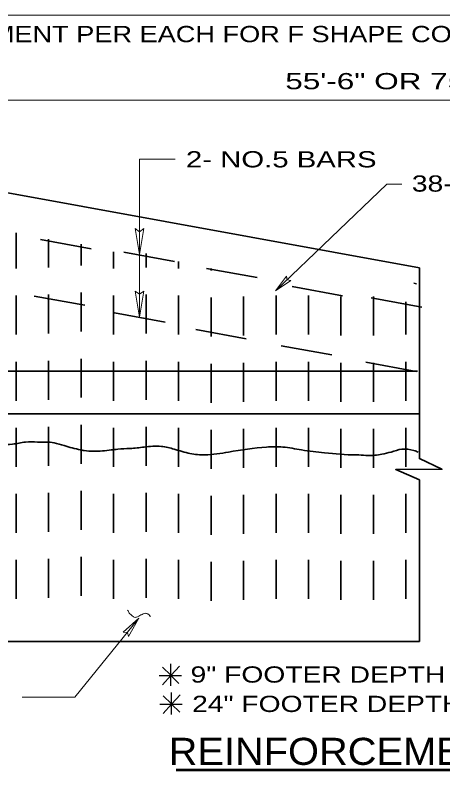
# Model space of a CAD drawing. Extents: x -15.1 to -7.9, y 13.6 to 23.8.
# Drawn here: x -13.275 to -11.694, y 16.811 to 19.599 of the extents above; entities that cross this region are included whole.
import ezdxf
from ezdxf.enums import TextEntityAlignment as Align

# ---------------------------------------------------------------- set-up
doc = ezdxf.new("R2010")
doc.units = 0
doc.header["$LTSCALE"] = 0.024
doc.linetypes.add('LONG_DASHED', pattern=[7.5, 6, -1.5])
for name, color, linetype, lineweight in [('1', 7, 'Continuous', 35), ('10', 7, 'Continuous', 13), ('12', 7, 'Continuous', 53)]:
    doc.layers.add(name, color=color, linetype=linetype, lineweight=lineweight)

msp = doc.modelspace()

# ---------------------------------------------------------------- linework, layer by layer
at = {"layer": '1'}
for p, q in [((-11.781, 18.666), (-13.76133, 19.026)), ((-12.99417, 18.73567), (-13.18083, 18.76967)), ((-12.686, 18.68917), (-12.87283, 18.723)), ((-12.3805, 18.6295), (-12.56717, 18.6635)), ((-11.79167, 18.60683), (-11.8015, 18.60867)), ((-12.0645, 18.56217), (-12.25133, 18.59617)), ((-13.0175, 18.52733), (-13.20417, 18.56133)), ((-11.772, 18.52083), (-11.95883, 18.55467)), ((-12.72083, 18.4655), (-12.90767, 18.4995)), ((-12.4205, 18.40333), (-12.60717, 18.43733)), ((-12.1045, 18.34383), (-12.29133, 18.37783)), ((-11.79233, 18.28283), (-11.97917, 18.31683)), ((-11.78733, 18.28383), (-14.11333, 18.28383)), ((-11.781, 18.12583), (-14.12133, 18.12583)), ((-11.781, 17.88333), (-11.781, 17.88417)), ((-11.781, 17.28567), (-14.12133, 17.28567))]:
    msp.add_line(p, q, dxfattribs=at)
at = {"layer": '1', "linetype": 'LONG_DASHED'}
for p, q in [((-13.27083, 17.44283), (-13.27083, 18.7945)), ((-13.15083, 17.4465), (-13.15083, 18.771)), ((-13.03083, 17.454), (-13.03083, 18.7535)), ((-12.91083, 17.44283), (-12.91083, 18.72417)), ((-12.79083, 17.4465), (-12.79083, 18.71833)), ((-12.67083, 17.44283), (-12.67083, 18.689)), ((-12.55067, 17.4355), (-12.55067, 18.66267)), ((-12.43067, 17.43917), (-12.43067, 18.642)), ((-12.31067, 17.44283), (-12.31067, 18.6215)), ((-12.19067, 17.44283), (-12.19067, 18.58933)), ((-12.07067, 17.43917), (-12.07067, 18.56883)), ((-11.95067, 17.43917), (-11.95067, 18.56)), ((-11.83067, 17.44283), (-11.83067, 18.5395))]:
    msp.add_line(p, q, dxfattribs=at)
at = {"layer": '1'}
msp.add_spline([(-14.12217, 18.03783), (-14.101, 18.03517), (-14.072, 18.03517), (-14.04283, 18.0405), (-14.0165, 18.0405), (-13.99267, 18.0405), (-13.95833, 18.0405), (-13.916, 18.0325), (-13.86833, 18.02733), (-13.8235, 18.02467), (-13.79167, 18.022), (-13.76267, 18.022), (-13.71767, 18.02733), (-13.678, 18.02983), (-13.63583, 18.0325), (-13.58817, 18.0325), (-13.5485, 18.02983), (-13.501, 18.022), (-13.456, 18.01417), (-13.40317, 18.00883), (-13.3635, 18.00883), (-13.329, 18.0115), (-13.28417, 18.01417), (-13.2365, 18.022), (-13.19167, 18.022), (-13.13083, 18.01933), (-13.09383, 18.00883), (-13.033, 17.993), (-13.01983, 17.99033), (-12.9855, 17.98783), (-12.91933, 17.993), (-12.8955, 17.99567), (-12.85067, 17.99833), (-12.79767, 18.0035), (-12.73433, 18.00617), (-12.68667, 17.99567), (-12.6285, 17.97983), (-12.573, 17.97467), (-12.48583, 17.98517), (-12.34567, 18.0035), (-12.28483, 18.0035), (-12.21617, 17.993), (-12.1315, 17.9825), (-12.01517, 17.97467), (-12.01267, 17.97467), (-12.00467, 17.97467), (-11.97033, 17.972), (-11.92, 17.97733), (-11.88567, 17.98517), (-11.846, 17.99567), (-11.801, 17.99033), (-11.78517, 17.98517)], degree=3, dxfattribs=at)
at = {"layer": '10'}
for p, q in [((-13.76867, 19.59917), (-8.606, 19.59917)), ((-10.09083, 19.28517), (-13.63867, 19.28517)), ((-11.90117, 18.97517), (-12.31217, 18.5805)), ((-11.84517, 18.975), (-11.90117, 18.975)), ((-12.83083, 18.8105), (-12.81483, 18.7145)), ((-12.83083, 18.8105), (-12.81483, 18.7985)), ((-12.79883, 18.8105), (-12.81483, 18.7145)), ((-12.79883, 18.8105), (-12.81483, 18.7985)), ((-12.2715, 18.63517), (-12.31217, 18.5805)), ((-12.2715, 18.63517), (-12.26983, 18.62133)), ((-12.256, 18.619), (-12.31217, 18.5805)), ((-12.256, 18.619), (-12.26983, 18.62133)), ((-12.83083, 18.57983), (-12.81483, 18.48383)), ((-12.83083, 18.57983), (-12.81483, 18.56783)), ((-12.79883, 18.57983), (-12.81483, 18.48383)), ((-12.79883, 18.57983), (-12.81483, 18.56783)), ((-13.05467, 17.07917), (-12.81767, 17.371)), ((-12.876, 17.3195), (-12.81767, 17.371)), ((-12.856, 17.30333), (-12.81767, 17.371)), ((-12.876, 17.3195), (-12.86, 17.31883)), ((-12.856, 17.30333), (-12.86, 17.31883)), ((-13.24883, 17.07917), (-13.05467, 17.07917))]:
    msp.add_line(p, q, dxfattribs=at)
at = {"layer": '10', "lineweight": 35}
for p, q in [((-11.781, 17.95983), (-11.781, 18.666)), ((-11.781, 17.28567), (-11.781, 17.88283))]:
    msp.add_line(p, q, dxfattribs=at)
at = {"layer": '10', "lineweight": 25}
for p, q in [((-12.69917, 17.12133), (-12.69917, 17.20333)), ((-12.73, 17.191), (-12.69983, 17.16117)), ((-12.6985, 17.16067), (-12.66767, 17.19417)), ((-12.74233, 17.1595), (-12.66033, 17.1595)), ((-12.7305, 17.12583), (-12.69967, 17.1595)), ((-12.6995, 17.15983), (-12.66933, 17.13)), ((-12.69633, 17.01533), (-12.69633, 17.09733)), ((-12.72733, 17.08483), (-12.697, 17.05517)), ((-12.69567, 17.05467), (-12.665, 17.08817)), ((-12.7395, 17.0535), (-12.6575, 17.0535)), ((-12.72767, 17.01983), (-12.697, 17.0535)), ((-12.69667, 17.05367), (-12.6665, 17.02383))]:
    msp.add_line(p, q, dxfattribs=at)
at = {"layer": '10'}
msp.add_lwpolyline([(-12.6835, 19.0665), (-12.81483, 19.0665), (-12.81483, 18.7145), (-12.81483, 18.48383)], dxfattribs=at)
at = {"layer": '10', "lineweight": 35}
msp.add_lwpolyline([(-11.78067, 17.882), (-11.868, 17.92017), (-11.6975, 17.9215), (-11.78067, 17.961)], dxfattribs=at)
at = {"layer": '10'}
msp.add_spline([(-12.77533, 17.37617), (-12.77683, 17.3805), (-12.77967, 17.38333), (-12.7825, 17.38633), (-12.78683, 17.38767), (-12.79117, 17.38917), (-12.797, 17.38917), (-12.80567, 17.38483), (-12.81, 17.38333), (-12.81717, 17.379), (-12.82867, 17.37483), (-12.8345, 17.37483), (-12.83883, 17.37767), (-12.8445, 17.382), (-12.85033, 17.38767), (-12.85467, 17.392), (-12.8575, 17.39917), (-12.859, 17.40067)], degree=3, dxfattribs=at)
at = {"layer": '12'}
msp.add_line((-12.67933, 16.811), (-10.37967, 16.811), dxfattribs=at)

# ---------------------------------------------------------------- texts
for s, height, width, p in [('PAYMENT PER EACH FOR F SHAPE CONCRETE TRAFFIC BARRIER SINGLE FACE END TRANSITION', 0.06001, 1.25, (-11.15954, 19.49917)), ('55\'-6" OR 75\'-6"', 0.06, 1.45, (-11.8605, 19.32517)), ('38-VERTICAL NO.5 BARS', 0.06001, 1.3, (-11.18542, 18.947)), ('REINFORCEMENT STEEL DETAIL', 0.1, 1.1, (-11.53471, 16.82958))]:
    msp.add_text(s, height=height, dxfattribs=dict(at, width=width)).set_placement(p, align=Align.CENTER)
for s, width, p in [('2- NO.5 BARS', 1.35, (-12.6435, 19.0365)), ('9" FOOTER DEPTH - VERTICAL BARS TO EXTEND 6" INTO FOOTER', 1.3, (-12.62642, 17.13342)), ('24" FOOTER DEPTH - VERTICAL BARS TO EXTEND 21" INTO FOOTER', 1.3, (-12.62067, 17.02492))]:
    msp.add_text(s, height=0.06001, dxfattribs=dict(at, width=width)).set_placement(p)

doc.saveas('drawing.dxf')
